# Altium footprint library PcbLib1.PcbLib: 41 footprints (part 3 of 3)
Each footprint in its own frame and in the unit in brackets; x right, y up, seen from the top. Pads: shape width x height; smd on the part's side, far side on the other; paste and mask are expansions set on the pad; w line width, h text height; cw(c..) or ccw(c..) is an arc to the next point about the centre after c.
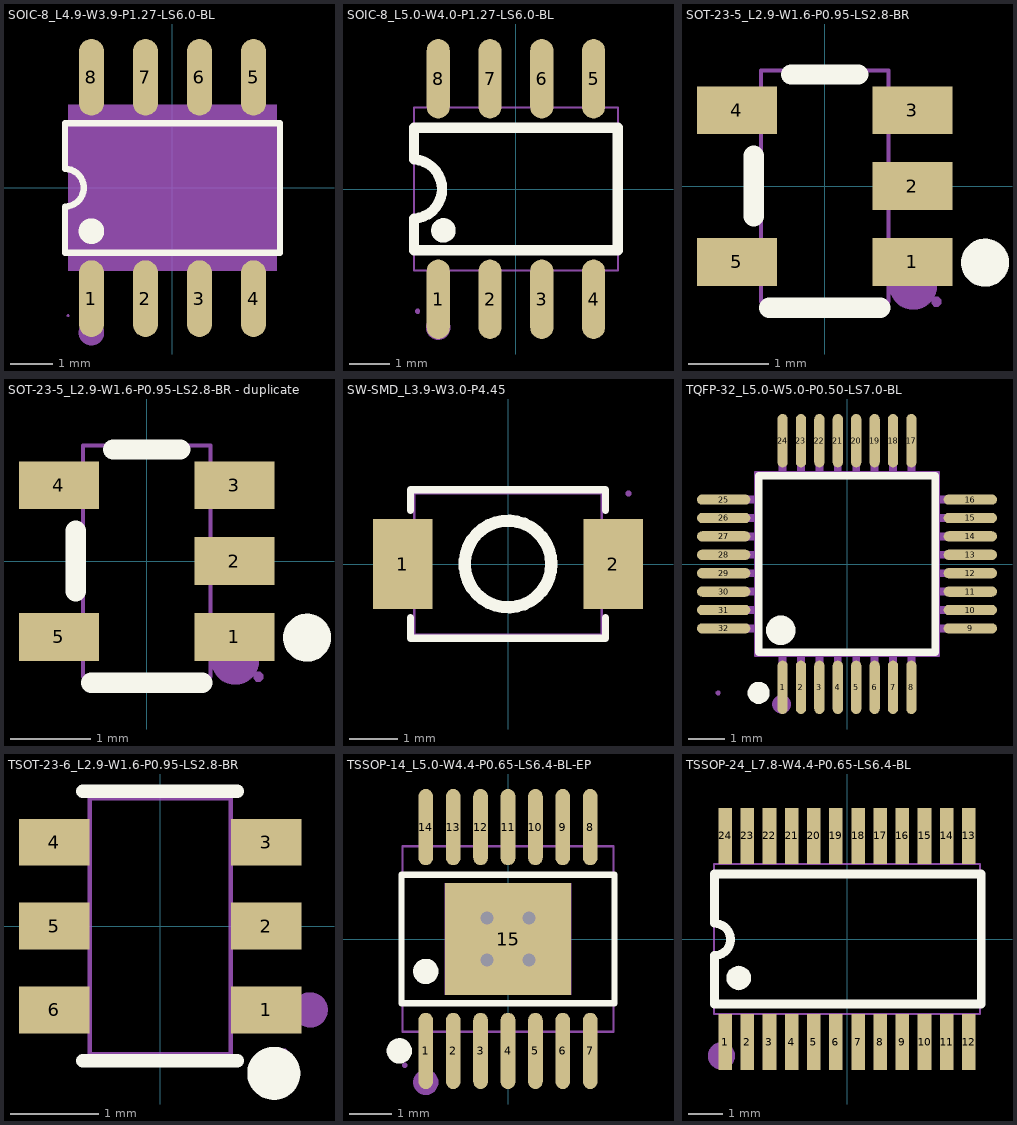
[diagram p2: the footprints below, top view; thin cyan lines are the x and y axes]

## SOIC-8_L4.9-W3.9-P1.27-LS6.0-BL [mm]
pads (8):
  oval 0.588x1.8 smd paste+0 mask+0.051: 1(-1.905,-2.6) 2(-0.635,-2.6) 3(0.635,-2.6) 4(1.905,-2.6) 5(1.905,2.6) 6(0.635,2.6) 7(-0.635,2.6) 8(-1.905,2.6)
Top Overlay:
  circle w0.3: c-1.905,-1.016 r0.15
  lines w0.15: -2.068,-1.521 -2.526,-1.521 ; -2.068,1.521 -2.526,1.521 ; -1.742,-1.521 -0.798,-1.521 ; -1.742,1.521 -0.798,1.521 ; -0.472,-1.521 0.472,-1.521 ; -0.472,1.521 0.472,1.521 ; 0.798,-1.521 1.742,-1.521 ; 0.798,1.521 1.742,1.521 ; 2.068,-1.521 2.526,-1.521 ; 2.068,1.521 2.526,1.521 ; -2.526,-1.521 2.526,-1.521 ; -2.526,-1.521 -2.526,-0.435 ccw(c-2.526,0.007) -2.526,0.449 -2.526,1.521 ; -2.526,1.521 2.526,1.521 ; 2.526,-1.521 2.526,1.521
Mechanical 5:
  circle w0.3: c-1.905,-3.4 r0.15
Mechanical 9:
  region: -2.45,-1.95 -2.45,1.95 2.45,1.95 2.45,-1.95
Mechanical 10:
  region: -2.115,-2.175 -2.115,-1.94 -1.695,-1.94 -1.695,-2.175
  region: -0.845,-2.175 -0.845,-1.94 -0.425,-1.94 -0.425,-2.175
  region: 0.425,-2.175 0.425,-1.94 0.845,-1.94 0.845,-2.175
  region: 1.695,-2.175 1.695,-1.94 2.115,-1.94 2.115,-2.175
  region: -2.115,2.175 -2.115,1.94 -1.695,1.94 -1.695,2.175
  region: -0.845,2.175 -0.845,1.94 -0.425,1.94 -0.425,2.175
  region: 0.425,2.175 0.425,1.94 0.845,1.94 0.845,2.175
  region: 1.695,2.175 1.695,1.94 2.115,1.94 2.115,2.175
Mechanical 11:
  region: -2.42,-3 -2.42,-3.012 -2.438,-3.03 -2.462,-3.03 -2.48,-3.012 -2.48,-3 -2.48,-2.988 -2.462,-2.97 -2.438,-2.97 -2.42,-2.988 -2.42,-3
Mechanical 12:
  region: -2.115,-3 -2.115,-2.165 -1.695,-2.165 -1.695,-3
  region: -0.845,-3 -0.845,-2.165 -0.425,-2.165 -0.425,-3
  region: 0.425,-3 0.425,-2.165 0.845,-2.165 0.845,-3
  region: 1.695,-3 1.695,-2.165 2.115,-2.165 2.115,-3
  region: -2.115,3 -2.115,2.165 -1.695,2.165 -1.695,3
  region: -0.845,3 -0.845,2.165 -0.425,2.165 -0.425,3
  region: 0.425,3 0.425,2.165 0.845,2.165 0.845,3
  region: 1.695,3 1.695,2.165 2.115,2.165 2.115,3

## SOIC-8_L5.0-W4.0-P1.27-LS6.0-BL [mil]
pads (8):
  oval 22.38x76.78 smd: 1(-75,-106.5) 2(-25,-106.5) 3(25,-106.5) 4(75,-106.5) 5(75,106.5) 6(25,106.5) 7(-25,106.5) 8(-75,106.5)
Top Overlay:
  circle w11.81: c-70,-40 r5.91
  lines w10: -98.43,-28.61 ccw(c-99.99,0) -98.23,28.59 ; -98.42,-28.61 -98.42,-59.05 98.42,-59.05 98.42,59.05 -98.42,59.05 -98.42,28.59
Mechanical 2:
  circle w11.81: c-75,-133.86 r5.91
Mechanical 6:
  lines w2: -98.42,-78.74 98.42,-78.74 98.42,78.74 -98.42,78.74 -98.42,-78.74
Mechanical 7:
  region: -83.07,-85.63 -83.07,-76.38 -66.93,-76.38 -66.93,-85.63
  region: -33.07,-85.63 -33.07,-76.38 -16.93,-76.38 -16.93,-85.63
  region: 16.93,-85.63 16.93,-76.38 33.07,-76.38 33.07,-85.63
  region: 66.93,-85.63 66.93,-76.38 83.07,-76.38 83.07,-85.63
  region: -83.07,76.38 -83.07,85.63 -66.93,85.63 -66.93,76.38
  region: -33.07,76.38 -33.07,85.63 -16.93,85.63 -16.93,76.38
  region: 16.93,76.38 16.93,85.63 33.07,85.63 33.07,76.38
  region: 66.93,76.38 66.93,85.63 83.07,85.63 83.07,76.38
Mechanical 8:
  region: -92.64,-118.11 -92.64,-119.09 -94.02,-120.47 -95.98,-120.47 -97.36,-119.09 -97.36,-118.11 -97.36,-117.13 -95.98,-115.75 -94.02,-115.75 -92.64,-117.13 -92.64,-118.11
Mechanical 9:
  region: -83.07,-118.11 -83.07,-85.24 -66.93,-85.24 -66.93,-118.11
  region: -33.07,-118.11 -33.07,-85.24 -16.93,-85.24 -16.93,-118.11
  region: 16.93,-118.11 16.93,-85.24 33.07,-85.24 33.07,-118.11
  region: 66.93,-118.11 66.93,-85.24 83.07,-85.24 83.07,-118.11
  region: -83.07,85.24 -83.07,118.11 -66.93,118.11 -66.93,85.24
  region: -33.07,85.24 -33.07,118.11 -16.93,118.11 -16.93,85.24
  region: 16.93,85.24 16.93,118.11 33.07,118.11 33.07,85.24
  region: 66.93,85.24 66.93,118.11 83.07,118.11 83.07,85.24

## SOT-23-5_L2.9-W1.6-P0.95-LS2.8-BR [mm]
pads (5):
  rect 1x0.6 smd paste+0 mask+0.05: 1(1.1,-0.95) 2(1.1,0) 3(1.1,0.95) 4(-1.1,0.95) 5(-1.1,-0.95)
Top Overlay:
  circle w0.3: c2.01,-0.96 r0.15
  lines w0.254: -0.889,-0.381 -0.889,0.381 ; -0.699,-1.524 0.698,-1.524 ; -0.422,1.397 0.422,1.397
Mechanical 2:
  circle w0.3: c1.11,-1.25 r0.15
Mechanical 6:
  lines w0.051: -0.8,-1.45 0.8,-1.45 0.8,1.45 -0.8,1.45 -0.8,-1.45
Mechanical 7:
  region: -0.79,-1.15 -0.96,-1.15 -0.96,-0.75 -0.79,-0.75
  region: -0.79,0.75 -0.96,0.75 -0.96,1.15 -0.79,1.15
  region: 0.96,-1.15 0.79,-1.15 0.79,-0.75 0.96,-0.75
  region: 0.96,0.75 0.79,0.75 0.79,1.15 0.96,1.15
  region: 0.96,-0.2 0.79,-0.2 0.79,0.2 0.96,0.2
Mechanical 8:
  region: 1.46,-1.45 1.46,-1.475 1.425,-1.51 1.375,-1.51 1.34,-1.475 1.34,-1.45 1.34,-1.425 1.375,-1.39 1.425,-1.39 1.46,-1.425 1.46,-1.45
Mechanical 9:
  region: -0.95,-1.15 -1.4,-1.15 -1.4,-0.75 -0.95,-0.75
  region: -0.95,0.75 -1.4,0.75 -1.4,1.15 -0.95,1.15
  region: 1.4,-1.15 0.95,-1.15 0.95,-0.75 1.4,-0.75
  region: 1.4,0.75 0.95,0.75 0.95,1.15 1.4,1.15
  region: 1.4,-0.2 0.95,-0.2 0.95,0.2 1.4,0.2

## SOT-23-5_L2.9-W1.6-P0.95-LS2.8-BR - duplicate [mm]
pads (5):
  rect 1x0.6 smd paste+0 mask+0.05: 1(1.1,-0.95) 2(1.1,0) 3(1.1,0.95) 4(-1.1,0.95) 5(-1.1,-0.95)
Top Overlay:
  circle w0.3: c2.01,-0.96 r0.15
  lines w0.254: -0.889,-0.381 -0.889,0.381 ; -0.699,-1.524 0.698,-1.524 ; -0.422,1.397 0.422,1.397
Mechanical 2:
  circle w0.3: c1.11,-1.25 r0.15
Mechanical 6:
  lines w0.051: -0.8,-1.45 0.8,-1.45 0.8,1.45 -0.8,1.45 -0.8,-1.45
Mechanical 7:
  region: -0.79,-1.15 -0.96,-1.15 -0.96,-0.75 -0.79,-0.75
  region: -0.79,0.75 -0.96,0.75 -0.96,1.15 -0.79,1.15
  region: 0.96,-1.15 0.79,-1.15 0.79,-0.75 0.96,-0.75
  region: 0.96,0.75 0.79,0.75 0.79,1.15 0.96,1.15
  region: 0.96,-0.2 0.79,-0.2 0.79,0.2 0.96,0.2
Mechanical 8:
  region: 1.46,-1.45 1.46,-1.475 1.425,-1.51 1.375,-1.51 1.34,-1.475 1.34,-1.45 1.34,-1.425 1.375,-1.39 1.425,-1.39 1.46,-1.425 1.46,-1.45
Mechanical 9:
  region: -0.95,-1.15 -1.4,-1.15 -1.4,-0.75 -0.95,-0.75
  region: -0.95,0.75 -1.4,0.75 -1.4,1.15 -0.95,1.15
  region: 1.4,-1.15 0.95,-1.15 0.95,-0.75 1.4,-0.75
  region: 1.4,0.75 0.95,0.75 0.95,1.15 1.4,1.15
  region: 1.4,-0.2 0.95,-0.2 0.95,0.2 1.4,0.2

## SW-SMD_L3.9-W3.0-P4.45 [mm]
pads (2):
  rect 1.23x1.86 smd: 1(-2.185,0) 2(2.185,0)
Top Overlay:
  circle w0.254: c0,0 r0.9
  lines w0.152: -2.026,-1.11 -2.026,-1.541 2.026,-1.541 2.026,-1.11 ; -2.026,1.11 -2.026,1.541 2.026,1.541 2.026,1.11
Mechanical 6:
  lines w0.051: -1.95,-1.465 1.95,-1.465 1.95,1.465 -1.95,1.465 -1.95,-1.465
Mechanical 8:
  region: 2.56,1.465 2.56,1.44 2.525,1.405 2.475,1.405 2.44,1.44 2.44,1.465 2.44,1.49 2.475,1.525 2.525,1.525 2.56,1.49 2.56,1.465
Mechanical 9:
  region: 2.5,0.65 2.5,-0.65 1.6,-0.65 1.6,0.65
  region: -2.5,0.65 -2.5,-0.65 -1.6,-0.65 -1.6,0.65

## TQFP-32_L5.0-W5.0-P0.50-LS7.0-BL [mm]
pads (32):
  oval 0.28x1.45 smd: 1(-1.75,-3.35) 2(-1.25,-3.35) 3(-0.75,-3.35) 4(-0.25,-3.35) 5(0.25,-3.35) 6(0.75,-3.35) 7(1.25,-3.35) 8(1.75,-3.35) 17(1.75,3.35) 18(1.25,3.35) 19(0.75,3.35) 20(0.25,3.35) 21(-0.25,3.35) 22(-0.75,3.35) 23(-1.25,3.35) 24(-1.75,3.35)
  oval 1.45x0.28 smd: 9(3.35,-1.75) 10(3.35,-1.25) 11(3.35,-0.75) 12(3.35,-0.25) 13(3.35,0.25) 14(3.35,0.75) 15(3.35,1.25) 16(3.35,1.75) 25(-3.35,1.75) 26(-3.35,1.25) 27(-3.35,0.75) 28(-3.35,0.25) 29(-3.35,-0.25) 30(-3.35,-0.75) 31(-3.35,-1.25) 32(-3.35,-1.75)
Top Overlay:
  lines w0.2: -2.4,-2.4 2.4,-2.4 2.4,2.4 -2.4,2.4 -2.4,-2.4
  lines w0.3: -2.4,-3.35 ccw(c-2.399,-3.5) -2.398,-3.35
  lines w0.4: -1.801,-1.6 ccw(c-1.798,-1.8) -1.796,-1.6
Mechanical 2:
  circle w0.254: c-1.778,-3.81 r0.127
Mechanical 6:
  lines w0.051: -2.5,-2.5 2.5,-2.5 2.5,2.5 -2.5,2.5 -2.5,-2.5
Mechanical 7:
  drawing of 32 lines, arcs and shapes, not listed
Mechanical 8:
  region: -3.44,-3.5 -3.44,-3.525 -3.475,-3.56 -3.525,-3.56 -3.56,-3.525 -3.56,-3.5 -3.56,-3.475 -3.525,-3.44 -3.475,-3.44 -3.44,-3.475 -3.44,-3.5
Mechanical 9:
  drawing of 32 lines, arcs and shapes, not listed

## TSOT-23-6_L2.9-W1.6-P0.95-LS2.8-BR [mm]
pads (6):
  rect 0.8x0.532 smd: 1(1.2,-0.95) 2(1.2,0) 3(1.2,0.95) 4(-1.2,0.95) 5(-1.2,0) 6(-1.2,-0.95)
Top Overlay:
  circle w0.3: c1.287,-1.669 r0.15
  lines w0.152: -0.876,-1.526 0.876,-1.526 ; -0.876,1.526 0.876,1.526
Mechanical 2:
  circle w0.2: c1.7,-0.95 r0.1
Mechanical 6:
  lines w0.051: -0.8,-1.45 0.8,-1.45 0.8,1.45 -0.8,1.45 -0.8,-1.45
Mechanical 7:
  region: -0.96,-1.15 -0.96,-0.75 -0.79,-0.75 -0.79,-1.15
  region: -0.96,-0.2 -0.96,0.2 -0.79,0.2 -0.79,-0.2
  region: -0.96,0.75 -0.96,1.15 -0.79,1.15 -0.79,0.75
  region: 0.79,0.75 0.79,1.15 0.96,1.15 0.96,0.75
  region: 0.79,-0.2 0.79,0.2 0.96,0.2 0.96,-0.2
  region: 0.79,-1.15 0.79,-0.75 0.96,-0.75 0.96,-1.15
Mechanical 8:
  region: 1.46,-1.45 1.46,-1.475 1.425,-1.51 1.375,-1.51 1.34,-1.475 1.34,-1.45 1.34,-1.425 1.375,-1.39 1.425,-1.39 1.46,-1.425 1.46,-1.45
Mechanical 9:
  region: -0.95,-1.15 -0.95,-0.75 -1.4,-0.75 -1.4,-1.15
  region: -0.95,-0.2 -0.95,0.2 -1.4,0.2 -1.4,-0.2
  region: -0.95,0.75 -0.95,1.15 -1.4,1.15 -1.4,0.75
  region: 0.95,0.75 0.95,1.15 1.4,1.15 1.4,0.75
  region: 0.95,-0.2 0.95,0.2 1.4,0.2 1.4,-0.2
  region: 0.95,-1.15 0.95,-0.75 1.4,-0.75 1.4,-1.15

## TSSOP-14_L5.0-W4.4-P0.65-LS6.4-BL-EP [mm]
pads (15):
  oval 0.35x1.809 smd: 1(-1.95,-2.655) 2(-1.3,-2.655) 3(-0.65,-2.655) 4(0,-2.655) 5(0.65,-2.655) 6(1.3,-2.655) 7(1.95,-2.655) 8(1.95,2.655) 9(1.3,2.655) 10(0.65,2.655) 11(0,2.655) 12(-0.65,2.655) 13(-1.3,2.655) 14(-1.95,2.655)
  rect 3x2.65 smd: 15(0,0)
via 0.495,-0.495 diameter 0.61 hole 0.305
via -0.495,-0.495 diameter 0.61 hole 0.305
via -0.495,0.495 diameter 0.61 hole 0.305
via 0.495,0.495 diameter 0.61 hole 0.305
Top Overlay:
  circle w0.3: c-2.577,-2.655 r0.15
  circle w0.3: c-1.95,-0.769 r0.15
  lines w0.152: -2.526,-1.521 2.526,-1.521 2.526,1.521 -2.526,1.521 -2.526,-1.521
Mechanical 2:
  circle w0.3: c-1.95,-3.4 r0.15
Mechanical 6:
  lines w0.051: -2.5,-2.2 2.5,-2.2 2.5,2.2 -2.5,2.2 -2.5,-2.2
Mechanical 7:
  region: 1.825,2.37 1.825,1.94 2.075,1.94 2.075,2.37
  region: 1.175,2.37 1.175,1.94 1.425,1.94 1.425,2.37
  region: 0.525,2.37 0.525,1.94 0.775,1.94 0.775,2.37
  region: -0.125,2.37 -0.125,1.94 0.125,1.94 0.125,2.37
  region: -0.775,2.37 -0.775,1.94 -0.525,1.94 -0.525,2.37
  region: -1.425,2.37 -1.425,1.94 -1.175,1.94 -1.175,2.37
  region: -2.075,2.37 -2.075,1.94 -1.825,1.94 -1.825,2.37
  region: 1.825,-2.37 1.825,-1.94 2.075,-1.94 2.075,-2.37
  region: 1.175,-2.37 1.175,-1.94 1.425,-1.94 1.425,-2.37
  region: 0.525,-2.37 0.525,-1.94 0.775,-1.94 0.775,-2.37
  region: -0.125,-2.37 -0.125,-1.94 0.125,-1.94 0.125,-2.37
  region: -0.775,-2.37 -0.775,-1.94 -0.525,-1.94 -0.525,-2.37
  region: -1.425,-2.37 -1.425,-1.94 -1.175,-1.94 -1.175,-2.37
  region: -2.075,-2.37 -2.075,-1.94 -1.825,-1.94 -1.825,-2.37
Mechanical 8:
  region: -2.39,-3 -2.39,-3.025 -2.425,-3.06 -2.475,-3.06 -2.51,-3.025 -2.51,-3 -2.51,-2.975 -2.475,-2.94 -2.425,-2.94 -2.39,-2.975 -2.39,-3
Mechanical 9:
  region: -1.5,-1.325 -1.5,1.325 1.5,1.325 1.5,-1.325
  region: 1.825,3 1.825,2.36 2.075,2.36 2.075,3
  region: 1.175,3 1.175,2.36 1.425,2.36 1.425,3
  region: 0.525,3 0.525,2.36 0.775,2.36 0.775,3
  region: -0.125,3 -0.125,2.36 0.125,2.36 0.125,3
  region: -0.775,3 -0.775,2.36 -0.525,2.36 -0.525,3
  region: -1.425,3 -1.425,2.36 -1.175,2.36 -1.175,3
  region: -2.075,3 -2.075,2.36 -1.825,2.36 -1.825,3
  region: 1.825,-3 1.825,-2.36 2.075,-2.36 2.075,-3
  region: 1.175,-3 1.175,-2.36 1.425,-2.36 1.425,-3
  region: 0.525,-3 0.525,-2.36 0.775,-2.36 0.775,-3
  region: -0.125,-3 -0.125,-2.36 0.125,-2.36 0.125,-3
  region: -0.775,-3 -0.775,-2.36 -0.525,-2.36 -0.525,-3
  region: -1.425,-3 -1.425,-2.36 -1.175,-2.36 -1.175,-3
  region: -2.075,-3 -2.075,-2.36 -1.825,-2.36 -1.825,-3

## TSSOP-24_L7.8-W4.4-P0.65-LS6.4-BL [mm]
pads (24):
  rect 0.4x1.65 smd: 1(-3.575,-3.023) 2(-2.925,-3.023) 3(-2.275,-3.023) 4(-1.625,-3.023) 5(-0.975,-3.023) 6(-0.325,-3.023) 7(0.325,-3.023) 8(0.975,-3.023) 9(1.625,-3.023) 10(2.275,-3.023) 11(2.925,-3.023) 12(3.575,-3.023) 13(3.575,3.023) 14(2.925,3.023) 15(2.275,3.023) 16(1.625,3.023) 17(0.975,3.023) 18(0.325,3.023) 19(-0.325,3.023) 20(-0.975,3.023) 21(-1.625,3.023) 22(-2.275,3.023) 23(-2.925,3.023) 24(-3.575,3.023)
Top Overlay:
  region: -3.529,-1.143 -3.52,-1.064 -3.494,-0.989 -3.452,-0.922 -3.396,-0.866 -3.329,-0.824 -3.254,-0.798 -3.175,-0.789 -3.096,-0.798 -3.021,-0.824 -2.954,-0.866 -2.898,-0.922 -2.856,-0.989 -2.83,-1.064 -2.821,-1.143 -2.83,-1.222 -2.856,-1.297 -2.898,-1.364 -2.954,-1.42 -3.021,-1.462 -3.096,-1.488 -3.175,-1.497 -3.254,-1.488 -3.329,-1.462 -3.396,-1.42 -3.452,-1.364 -3.494,-1.297 -3.52,-1.222
  lines w0.254: -3.886,0.457 cw(c-3.886,-0.013) -3.886,-0.483 -3.886,-1.753 -3.886,-1.905 3.937,-1.905 3.937,1.905 -3.886,1.905 -3.886,1.753 -3.886,0.483
Mechanical 2:
  circle w0.4: c-3.683,-3.429 r0.2
Mechanical 6:
  lines w0.051: -3.9,-2.2 -3.9,2.2 3.9,2.2 3.9,-2.2 -3.9,-2.2
Mechanical 7:
  region: -0.225,2.588 -0.425,2.588 -0.425,2.188 -0.225,2.188
  region: -0.875,2.588 -1.075,2.588 -1.075,2.188 -0.875,2.188
  region: -1.525,2.588 -1.725,2.588 -1.725,2.188 -1.525,2.188
  region: -2.175,2.588 -2.375,2.588 -2.375,2.188 -2.175,2.188
  region: -2.825,2.588 -3.025,2.588 -3.025,2.188 -2.825,2.188
  region: -3.475,2.588 -3.675,2.588 -3.675,2.188 -3.475,2.188
  region: 3.675,2.588 3.475,2.588 3.475,2.188 3.675,2.188
  region: 3.025,2.588 2.825,2.588 2.825,2.188 3.025,2.188
  region: 2.375,2.588 2.175,2.588 2.175,2.188 2.375,2.188
  region: 1.725,2.588 1.525,2.588 1.525,2.188 1.725,2.188
  region: 1.075,2.588 0.875,2.588 0.875,2.188 1.075,2.188
  region: 0.425,2.588 0.225,2.588 0.225,2.188 0.425,2.188
  region: 0.225,-2.588 0.425,-2.588 0.425,-2.188 0.225,-2.188
  region: 0.875,-2.588 1.075,-2.588 1.075,-2.188 0.875,-2.188
  region: 1.525,-2.588 1.725,-2.588 1.725,-2.188 1.525,-2.188
  region: 2.175,-2.588 2.375,-2.588 2.375,-2.188 2.175,-2.188
  region: 2.825,-2.588 3.025,-2.588 3.025,-2.188 2.825,-2.188
  region: 3.475,-2.588 3.675,-2.588 3.675,-2.188 3.475,-2.188
  region: -3.675,-2.588 -3.475,-2.588 -3.475,-2.188 -3.675,-2.188
  region: -3.025,-2.588 -2.825,-2.588 -2.825,-2.188 -3.025,-2.188
  region: -2.375,-2.588 -2.175,-2.588 -2.175,-2.188 -2.375,-2.188
  region: -1.725,-2.588 -1.525,-2.588 -1.525,-2.188 -1.725,-2.188
  region: -1.075,-2.588 -0.875,-2.588 -0.875,-2.188 -1.075,-2.188
  region: -0.425,-2.588 -0.225,-2.588 -0.225,-2.188 -0.425,-2.188
Mechanical 8:
  region: -3.84,-3.186 -3.84,-3.211 -3.875,-3.246 -3.925,-3.246 -3.96,-3.211 -3.96,-3.186 -3.96,-3.161 -3.925,-3.126 -3.875,-3.126 -3.84,-3.161 -3.84,-3.186
Mechanical 9:
  region: -0.225,2.586 -0.425,2.586 -0.425,3.186 -0.225,3.186
  region: -0.875,2.586 -1.075,2.586 -1.075,3.186 -0.875,3.186
  region: -1.525,2.586 -1.725,2.586 -1.725,3.186 -1.525,3.186
  region: -2.175,2.586 -2.375,2.586 -2.375,3.186 -2.175,3.186
  region: -2.825,2.586 -3.025,2.586 -3.025,3.186 -2.825,3.186
  region: -3.475,2.586 -3.675,2.586 -3.675,3.186 -3.475,3.186
  region: 3.675,2.586 3.475,2.586 3.475,3.186 3.675,3.186
  region: 3.025,2.586 2.825,2.586 2.825,3.186 3.025,3.186
  region: 2.375,2.586 2.175,2.586 2.175,3.186 2.375,3.186
  region: 1.725,2.586 1.525,2.586 1.525,3.186 1.725,3.186
  region: 1.075,2.586 0.875,2.586 0.875,3.186 1.075,3.186
  region: 0.425,2.586 0.225,2.586 0.225,3.186 0.425,3.186
  region: 0.225,-2.586 0.425,-2.586 0.425,-3.186 0.225,-3.186
  region: 0.875,-2.586 1.075,-2.586 1.075,-3.186 0.875,-3.186
  region: 1.525,-2.586 1.725,-2.586 1.725,-3.186 1.525,-3.186
  region: 2.175,-2.586 2.375,-2.586 2.375,-3.186 2.175,-3.186
  region: 2.825,-2.586 3.025,-2.586 3.025,-3.186 2.825,-3.186
  region: 3.475,-2.586 3.675,-2.586 3.675,-3.186 3.475,-3.186
  region: -3.675,-2.586 -3.475,-2.586 -3.475,-3.186 -3.675,-3.186
  region: -3.025,-2.586 -2.825,-2.586 -2.825,-3.186 -3.025,-3.186
  region: -2.375,-2.586 -2.175,-2.586 -2.175,-3.186 -2.375,-3.186
  region: -1.725,-2.586 -1.525,-2.586 -1.525,-3.186 -1.725,-3.186
  region: -1.075,-2.586 -0.875,-2.586 -0.875,-3.186 -1.075,-3.186
  region: -0.425,-2.586 -0.225,-2.586 -0.225,-3.186 -0.425,-3.186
